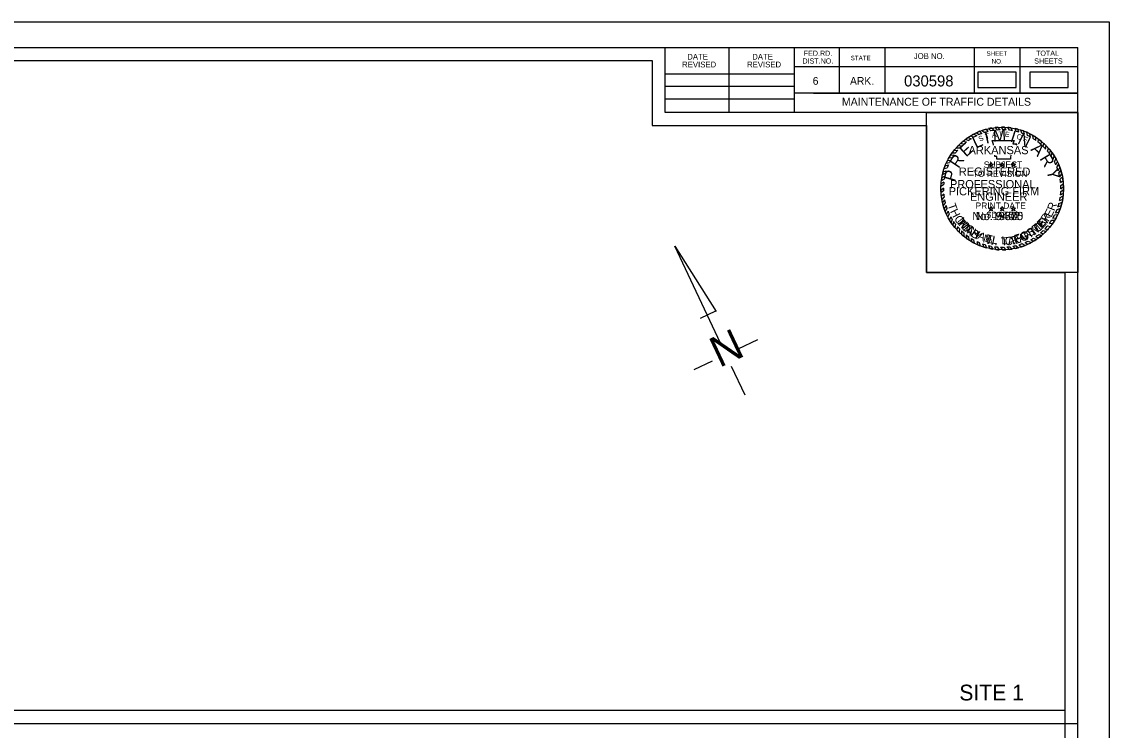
# Model space of a CAD drawing. Extents: x 1368648 to 1927880, y -1037443 to 380209.
# Drawn here: x 1376651 to 1377477, y 379215 to 379753 of the extents above; entities that cross this region are included whole.
import ezdxf

# ---------------------------------------------------------------- set-up
doc = ezdxf.new("R2010")
doc.units = 0
for name, color, linetype in [('Default', 7, 'Continuous'), ('R_Border', 7, 'Continuous'), ('R_Border Notes', 7, 'Continuous'), ('R_Border Title', 7, 'Continuous'), ('R_Draft', 7, 'Continuous'), ('R_No Plot', 7, 'Continuous'), ('STAMP_PE_CRAFTON', 7, 'Continuous'), ('STAMP_PE_FOSTER', 7, 'Continuous'), ('STAMP_PE_SEAL-INFO', 7, 'Continuous'), ('STAMP_PE_TAEGTMEYER', 7, 'Continuous'), ('STAMP_PE_TXT', 7, 'Continuous'), ('STAMP_PRELIMINARY', 7, 'Continuous')]:
    doc.layers.add(name, color=color, linetype=linetype)

msp = doc.modelspace()

# ---------------------------------------------------------------- linework, layer by layer
at = {"layer": 'Default'}
for points in [[(1377377.14, 379702.78), (1377406.31, 379702.78), (1377406.31, 379714.33), (1377377.14, 379714.33)], [(1377416.49, 379702.78), (1377445.66, 379702.78), (1377445.66, 379714.33), (1377416.49, 379714.33)]]:
    msp.add_lwpolyline(points, close=True, dxfattribs=at)
at = {"layer": 'R_Border'}
for p, q in [((1375872.18, 379733.26), (1377453.08, 379733.26)), ((1377139.88, 379683.86), (1377139.88, 379733.26)), ((1377188.28, 379683.86), (1377188.28, 379733.26)), ((1377237.58, 379733.26), (1377237.58, 379683.86)), ((1377271.78, 379733.26), (1377271.78, 379698.56)), ((1377306.48, 379733.26), (1377306.48, 379698.56)), ((1377374.38, 379733.26), (1377374.38, 379698.56)), ((1377409.08, 379733.26), (1377409.08, 379698.56)), ((1377453.08, 378705.96), (1377453.08, 379733.26)), ((1377453.08, 379718.56), (1377237.58, 379718.56)), ((1377453.08, 379718.66), (1377453.08, 379718.66)), ((1377139.88, 379713.16), (1377237.58, 379713.16)), ((1377139.88, 379703.86), (1377237.58, 379703.86)), ((1377453.08, 379698.56), (1377237.58, 379698.56)), ((1377252.38, 379698.56), (1377453.08, 379698.56)), ((1377139.88, 379694.16), (1377237.58, 379694.16)), ((1377453.08, 379683.86), (1377139.88, 379683.86)), ((1377453.08, 379219.61), (1375872.18, 379219.61))]:
    msp.add_line(p, q, dxfattribs=at)
at = {"layer": 'R_Draft'}
for p, q in [((1377147.07, 379582.19), (1377178.49, 379532.68)), ((1377181.8, 379508.63), (1377147.07, 379582.19)), ((1377166.62, 379527.56), (1377178.31, 379533.08)), ((1377195.18, 379504.34), (1377210.08, 379511.38)), ((1377161.7, 379488.53), (1377175.65, 379495.12)), ((1377200.43, 379469.16), (1377190.22, 379490.79))]:
    msp.add_line(p, q, dxfattribs=at)
at = {"layer": 'R_No Plot'}
for points in [[(1375810.14, 379752.73), (1377476.84, 379752.73), (1377476.84, 378686.04), (1375810.14, 378686.04)], [(1377443.08, 379229.61), (1375882.18, 379229.61), (1375882.18, 379723.26), (1377129.88, 379723.26), (1377129.88, 379673.86), (1377217.58, 379673.86), (1377338.08, 379673.86), (1377338.08, 379562.19), (1377443.08, 379562.19)], [(1377443.08, 379229.61), (1375882.18, 379229.61), (1375882.18, 379723.26), (1377129.88, 379723.26), (1377129.88, 379673.86), (1377217.58, 379673.86), (1377338.08, 379673.86), (1377338.08, 379562.19), (1377443.08, 379562.19)], [(1377443.08, 379229.61), (1375882.18, 379229.61), (1375882.18, 379723.26), (1377129.88, 379723.26), (1377129.88, 379673.86), (1377217.58, 379673.86), (1377338.08, 379673.86), (1377338.08, 379562.19), (1377443.08, 379562.19)], [(1377443.08, 379229.61), (1375882.18, 379229.61), (1375882.18, 379723.26), (1377129.88, 379723.26), (1377129.88, 379673.86), (1377217.58, 379673.86), (1377338.08, 379673.86), (1377338.08, 379562.19), (1377443.08, 379562.19)], [(1377443.08, 379229.61), (1375882.18, 379229.61), (1375882.18, 379723.26), (1377129.88, 379723.26), (1377129.88, 379673.86), (1377217.58, 379673.86), (1377338.08, 379673.86), (1377338.08, 379562.19), (1377443.08, 379562.19)], [(1377443.08, 379229.61), (1375882.18, 379229.61), (1375882.18, 379723.26), (1377129.88, 379723.26), (1377129.88, 379673.86), (1377217.58, 379673.86), (1377338.08, 379673.86), (1377338.08, 379562.19), (1377443.08, 379562.19)], [(1377443.08, 379229.61), (1375882.18, 379229.61), (1375882.18, 379723.26), (1377129.88, 379723.26), (1377129.88, 379673.86), (1377217.58, 379673.86), (1377338.08, 379673.86), (1377338.08, 379562.19), (1377443.08, 379562.19)], [(1375882.18, 379723.26), (1377129.88, 379723.26), (1377129.88, 379673.86), (1377217.58, 379673.86), (1377338.08, 379673.86), (1377338.08, 379562.19), (1377443.08, 379562.19), (1377443.08, 378715.96), (1375882.18, 378715.96)], [(1377338.08, 379683.86), (1377453.08, 379683.86), (1377453.08, 379562.19), (1377338.08, 379562.19)]]:
    msp.add_lwpolyline(points, close=True, dxfattribs=at)
at = {"layer": 'STAMP_PE_SEAL-INFO'}
for p, q in [((1377371.7, 379666.1), (1377373.86, 379664.99)), ((1377373.94, 379667.36), (1377376.26, 379666.23)), ((1377376.1, 379668.42), (1377378.04, 379667.04)), ((1377378.64, 379669.49), (1377380.11, 379667.87)), ((1377380.37, 379670.13), (1377382.28, 379668.61)), ((1377383.33, 379671.04), (1377384.77, 379669.31)), ((1377385.27, 379671.53), (1377387.05, 379669.81)), ((1377387.68, 379672.01), (1377389.18, 379670.17)), ((1377390.26, 379672.38), (1377391.66, 379670.46)), ((1377393.94, 379670.61), (1377392.38, 379672.57)), ((1377396.42, 379670.63), (1377395.03, 379672.68)), ((1377398.71, 379670.53), (1377397.42, 379672.65)), ((1377401.24, 379670.27), (1377399.78, 379672.49)), ((1377403.37, 379669.95), (1377402.09, 379672.23)), ((1377406.18, 379669.36), (1377405.31, 379671.65)), ((1377408.19, 379668.81), (1377407.4, 379671.16)), ((1377410.45, 379668.08), (1377409.74, 379670.48)), ((1377412.54, 379667.28), (1377411.82, 379669.76)), ((1377414.85, 379666.25), (1377414.34, 379668.74)), ((1377417.08, 379665.11), (1377416.64, 379667.65)), ((1377419.02, 379663.97), (1377418.82, 379666.48)), ((1377362.39, 379658.8), (1377365.11, 379658.59)), ((1377364.06, 379660.41), (1377366.36, 379659.72)), ((1377365.78, 379661.92), (1377368.43, 379661.41)), ((1377367.67, 379663.55), (1377369.94, 379662.53)), ((1377369.77, 379664.88), (1377371.98, 379663.87)), ((1377387.94, 379662.52), (1377404.66, 379662.52)), ((1377388.55, 379660.99), (1377387.94, 379662.52)), ((1377389.07, 379659.5), (1377388.55, 379660.99)), ((1377389.1, 379658.93), (1377389.07, 379659.5)), ((1377404.66, 379662.52), (1377403.54, 379660.07)), ((1377403.54, 379660.07), (1377406.7, 379660.07)), ((1377406.7, 379660.07), (1377405.98, 379658.93)), ((1377421.19, 379662.54), (1377421.03, 379665.12)), ((1377422.99, 379661.21), (1377423.16, 379663.64)), ((1377425.22, 379659.35), (1377425.32, 379661.96)), ((1377426.79, 379657.88), (1377427.13, 379660.38)), ((1377428.58, 379656.02), (1377428.91, 379658.65)), ((1377355.25, 379649.45), (1377357.7, 379649.55)), ((1377356.48, 379651.45), (1377359.06, 379651.62)), ((1377357.65, 379653.17), (1377360.18, 379653.15)), ((1377359.04, 379655.02), (1377361.79, 379655.13)), ((1377360.77, 379657.08), (1377363.38, 379656.88)), ((1377390.06, 379650.38), (1377389.93, 379651.47)), ((1377391.63, 379650.38), (1377390.06, 379650.38)), ((1377391.63, 379648.23), (1377391.63, 379650.38)), ((1377401.86, 379649.92), (1377401.78, 379648.23)), ((1377402.25, 379651.47), (1377401.86, 379649.92)), ((1377429.95, 379654.44), (1377430.63, 379656.79)), ((1377431.57, 379652.35), (1377432.25, 379654.85)), ((1377432.67, 379650.77), (1377433.56, 379653.09)), ((1377434.21, 379648.29), (1377435.12, 379650.74)), ((1377351.48, 379641.19), (1377353.91, 379641.87)), ((1377352.23, 379643.22), (1377354.76, 379643.95)), ((1377353.15, 379645.38), (1377355.67, 379645.9)), ((1377354.09, 379647.33), (1377356.59, 379647.65)), ((1377401.78, 379648.23), (1377391.63, 379648.23)), ((1377435.21, 379646.45), (1377436.34, 379648.68)), ((1377436.36, 379644.03), (1377437.49, 379646.46)), ((1377437.06, 379642.35), (1377438.38, 379644.52)), ((1377438.04, 379639.6), (1377439.39, 379641.98)), ((1377351.57, 379633.11), (1377349.34, 379632)), ((1377352, 379635.41), (1377349.67, 379634.16)), ((1377350.18, 379636.64), (1377352.53, 379637.6)), ((1377350.7, 379638.68), (1377353.09, 379639.52)), ((1377438.58, 379637.78), (1377440.05, 379640.04)), ((1377439.24, 379634.99), (1377440.84, 379637.22)), ((1377439.59, 379633.09), (1377441.36, 379634.85)), ((1377351.01, 379626.34), (1377348.98, 379624.67)), ((1377351.09, 379628.81), (1377348.99, 379627.53)), ((1377351.28, 379630.94), (1377349.09, 379629.53)), ((1377351.04, 379624.31), (1377349.09, 379622.68)), ((1377439.92, 379630.54), (1377441.78, 379632.22)), ((1377440.08, 379628.45), (1377442.03, 379629.91)), ((1377440.09, 379623.83), (1377442.18, 379625.22)), ((1377440.14, 379625.86), (1377442.17, 379627.47)), ((1377351.21, 379621.83), (1377349.35, 379620.05)), ((1377351.47, 379619.69), (1377349.7, 379617.82)), ((1377351.86, 379617.39), (1377350.16, 379615.55)), ((1377439.18, 379616.86), (1377441.46, 379617.84)), ((1377439.64, 379619.36), (1377441.85, 379620.46)), ((1377439.89, 379621.3), (1377442.06, 379622.59)), ((1377352.33, 379615.3), (1377350.77, 379613.22)), ((1377352.95, 379613.06), (1377351.48, 379610.97)), ((1377353.65, 379610.95), (1377352.25, 379608.89)), ((1377354.48, 379608.81), (1377353.18, 379606.7)), ((1377436.17, 379607.66), (1377438.61, 379608.14)), ((1377437.24, 379610.23), (1377439.65, 379610.89)), ((1377437.91, 379612.13), (1377440.36, 379613.14)), ((1377438.64, 379614.6), (1377441, 379615.61)), ((1377355.34, 379606.9), (1377354.21, 379604.59)), ((1377356.52, 379604.61), (1377355.56, 379602.16)), ((1377357.7, 379602.59), (1377356.78, 379600.23)), ((1377358.71, 379601.03), (1377358.16, 379598.27)), ((1377431.44, 379599.61), (1377433.96, 379599.63)), ((1377433.14, 379602.08), (1377435.53, 379602.05)), ((1377434, 379603.49), (1377436.5, 379603.76)), ((1377435.36, 379605.98), (1377437.8, 379606.32)), ((1377360.11, 379599.08), (1377359.6, 379596.42)), ((1377361.63, 379597.19), (1377361.2, 379594.59)), ((1377363.14, 379595.5), (1377362.84, 379592.89)), ((1377364.76, 379593.87), (1377364.61, 379591.23)), ((1377366.48, 379592.31), (1377366.46, 379589.67)), ((1377423.33, 379591.2), (1377425.67, 379590.47)), ((1377424.68, 379592.32), (1377427.04, 379591.67)), ((1377426.71, 379594.18), (1377428.92, 379593.49)), ((1377427.99, 379595.48), (1377430.37, 379595.05)), ((1377429.9, 379597.64), (1377432.21, 379597.24)), ((1377368.28, 379590.84), (1377368.37, 379588.22)), ((1377369.97, 379589.59), (1377370.15, 379587)), ((1377372.11, 379588.18), (1377372.41, 379585.62)), ((1377373.86, 379587.15), (1377374.31, 379584.59)), ((1377376.26, 379585.9), (1377377.05, 379583.3)), ((1377378.13, 379585.06), (1377378.99, 379582.51)), ((1377380.59, 379584.1), (1377381.63, 379581.59)), ((1377382.64, 379583.42), (1377383.77, 379580.98)), ((1377408.34, 379583.37), (1377410.42, 379581.88)), ((1377410.8, 379584.18), (1377413.02, 379582.84)), ((1377412.9, 379585.01), (1377415.02, 379583.7)), ((1377415.2, 379586.05), (1377417.62, 379584.99)), ((1377417.24, 379587.12), (1377419.32, 379585.95)), ((1377419.31, 379588.34), (1377421.56, 379587.37)), ((1377421.03, 379589.48), (1377423.22, 379588.54)), ((1377385.18, 379582.73), (1377386.24, 379580.4)), ((1377387.16, 379582.3), (1377388.4, 379580.01)), ((1377389.67, 379581.89), (1377390.86, 379579.69)), ((1377391.85, 379581.66), (1377393.22, 379579.51)), ((1377394.27, 379581.52), (1377395.78, 379579.46)), ((1377396.57, 379581.51), (1377398.29, 379579.53)), ((1377399.16, 379581.65), (1377400.79, 379579.75)), ((1377401.35, 379581.88), (1377403.22, 379580.09)), ((1377403.58, 379582.23), (1377405.52, 379580.53)), ((1377406.04, 379582.75), (1377407.93, 379581.12))]:
    msp.add_line(p, q, dxfattribs=at)
for radius, start, end in [(46.61, 117.65441, 120.80988), (44.57, 115.68692, 119.15827), (46.61, 111.31242, 114.70259), (44.57, 110.30864, 113.16588), (46.61, 105.23389, 109.03519), (44.57, 104.03521, 107.36155), (46.61, 99.75254, 102.77648), (44.57, 98.25799, 101.03289), (46.61, 93.93815, 96.55172), (44.57, 92.11016, 95.03666), (46.61, 87.72979, 90.67067), (44.57, 85.96279, 88.9097), (46.61, 81.97315, 84.82355), (44.57, 79.92642, 82.69597), (46.61, 75.31251, 77.94263), (44.57, 73.55748, 76.23144), (46.61, 69.60611, 72.30577), (44.57, 67.62483, 70.50398), (46.61, 63.13288, 66.2704), (44.57, 61.15575, 64.37837), (46.61, 56.90029, 60.09423), (46.61, 135.40208, 138.30314), (44.57, 133.13306, 136.25623), (46.61, 129.73259, 132.53764), (44.57, 127.52969, 130.96829), (46.61, 123.61993, 126.59063), (44.57, 121.97456, 125.11001), (44.57, 54.92383, 58.27016), (44.57, 48.30163, 52.03953), (46.61, 50.3492, 53.71593), (44.57, 42.22116, 45.55119), (46.61, 44.3405, 47.39292), (46.61, 147.00719, 149.89904), (46.61, 141.60556, 144.44865), (44.57, 145.01972, 148.21036), (44.57, 139.30101, 142.58729), (44.57, 36.13503, 39.53106), (46.61, 38.12472, 41.23157), (44.57, 29.90321, 33.66454), (46.61, 31.96138, 35.42937), (46.61, 158.40766, 161.07015), (46.61, 152.86398, 155.51889), (44.57, 156.34018, 159.23194), (44.57, 151.03153, 153.57304), (44.57, 23.77322, 27.22114), (46.61, 25.93909, 29.01247), (44.57, 17.68022, 21.42509), (46.61, 19.95381, 23.31409), (46.61, 170.0003, 172.68778), (46.61, 164.3068, 166.89395), (44.57, 167.90481, 170.90393), (44.57, 162.43309, 165.00133), (44.57, 11.54445, 15.23639), (44.57, 5.7599, 9.06056), (46.61, 13.84205, 17.44468), (46.61, 7.58519, 10.86211), (46.61, 181.72508, 184.16255), (46.61, 175.74093, 178.2066), (44.57, 179.64537, 182.26333), (44.57, 173.73, 176.47337), (44.57, 359.73289, 3.06392), (46.61, 1.72155, 4.72681), (46.61, 355.71562, 358.95694), (46.61, 187.42037, 190.19271), (44.57, 185.45389, 188.23401), (44.57, 191.22736, 193.98583), (44.57, 348.07782, 351.34355), (44.57, 353.86319, 357.12742), (46.61, 349.83047, 353.08845), (46.61, 193.03695, 195.99732), (46.61, 198.89671, 201.62812), (44.57, 196.96751, 199.83526), (44.57, 202.77613, 205.47915), (44.57, 335.6038, 339.18578), (44.57, 341.77699, 345.09248), (46.61, 337.38367, 340.99332), (46.61, 343.89247, 347.03502), (46.61, 204.54793, 207.43282), (46.61, 210.86355, 213.65709), (44.57, 208.78826, 211.79343), (44.57, 214.18375, 217.27474), (44.57, 323.58513, 327.44069), (46.61, 325.44052, 328.98725), (44.57, 329.55488, 333.20757), (46.61, 331.40371, 334.93315), (46.61, 216.61154, 219.49098), (46.61, 222.47995, 225.38008), (44.57, 220.39088, 223.30564), (46.61, 228.36648, 231.34802), (44.57, 226.24938, 229.24068), (44.57, 304.82299, 308.51428), (44.57, 310.77436, 314.31605), (46.61, 312.45177, 315.66328), (44.57, 316.65308, 320.37109), (46.61, 318.28455, 321.80429), (44.57, 232.22904, 234.93361), (46.61, 234.29502, 236.94517), (44.57, 238.22227, 240.83529), (46.61, 240.1977, 242.86128), (44.57, 244.32043, 246.94859), (46.61, 246.57598, 249.15579), (44.57, 250.34912, 253.12157), (44.57, 286.64233, 289.97826), (44.57, 292.87452, 296.11851), (46.61, 294.64808, 298.21662), (44.57, 299.07679, 302.17235), (46.61, 300.62101, 303.87026), (46.61, 306.37206, 310.20799), (46.61, 252.59667, 255.32518), (44.57, 256.50505, 259.11916), (46.61, 258.44328, 261.13983), (44.57, 262.37828, 265.20115), (46.61, 264.19784, 267.10092), (44.57, 268.3215, 271.27698), (46.61, 270.25484, 273.33609), (44.57, 274.61565, 277.44863), (46.61, 276.42389, 279.43574), (44.57, 280.34588, 283.58137), (46.61, 282.31994, 285.37019), (46.61, 288.57086, 291.97334)]:
    msp.add_arc((1377395.58, 379626.07), radius, start, end, dxfattribs=at)
at = {"layer": 'STAMP_PE_TXT'}
for p, q in [((1377386.47, 379643.93), (1377385.48, 379644.65)), ((1377385.48, 379644.65), (1377386.71, 379644.65)), ((1377386.1, 379642.76), (1377386.47, 379643.93)), ((1377387.09, 379643.48), (1377386.1, 379642.76)), ((1377386.71, 379644.65), (1377387.09, 379645.81)), ((1377387.09, 379645.81), (1377387.47, 379644.65)), ((1377388.08, 379642.76), (1377387.09, 379643.48)), ((1377387.47, 379644.65), (1377388.69, 379644.65)), ((1377388.69, 379644.65), (1377387.7, 379643.93)), ((1377387.7, 379643.93), (1377388.08, 379642.76)), ((1377394.96, 379643.93), (1377393.97, 379644.65)), ((1377393.97, 379644.65), (1377395.2, 379644.65)), ((1377394.59, 379642.76), (1377394.96, 379643.93)), ((1377395.58, 379643.48), (1377394.59, 379642.76)), ((1377395.2, 379644.65), (1377395.58, 379645.81)), ((1377395.58, 379645.81), (1377395.96, 379644.65)), ((1377396.57, 379642.76), (1377395.58, 379643.48)), ((1377395.96, 379644.65), (1377397.18, 379644.65)), ((1377397.18, 379644.65), (1377396.19, 379643.93)), ((1377396.19, 379643.93), (1377396.57, 379642.76)), ((1377403.45, 379643.93), (1377402.46, 379644.65)), ((1377402.46, 379644.65), (1377403.69, 379644.65)), ((1377403.07, 379642.76), (1377403.45, 379643.93)), ((1377404.07, 379643.48), (1377403.07, 379642.76)), ((1377403.69, 379644.65), (1377404.07, 379645.81)), ((1377404.07, 379645.81), (1377404.45, 379644.65)), ((1377405.06, 379642.76), (1377404.07, 379643.48)), ((1377404.45, 379644.65), (1377405.67, 379644.65)), ((1377405.67, 379644.65), (1377404.68, 379643.93)), ((1377404.68, 379643.93), (1377405.06, 379642.76)), ((1377386.47, 379610.39), (1377385.48, 379611.11)), ((1377385.48, 379611.11), (1377386.71, 379611.11)), ((1377386.1, 379609.22), (1377386.47, 379610.39)), ((1377387.09, 379609.95), (1377386.1, 379609.22)), ((1377386.71, 379611.11), (1377387.09, 379612.28)), ((1377387.09, 379612.28), (1377387.47, 379611.11)), ((1377388.08, 379609.22), (1377387.09, 379609.95)), ((1377387.47, 379611.11), (1377388.69, 379611.11)), ((1377388.69, 379611.11), (1377387.7, 379610.39)), ((1377387.7, 379610.39), (1377388.08, 379609.22)), ((1377394.96, 379610.39), (1377393.97, 379611.11)), ((1377393.97, 379611.11), (1377395.2, 379611.11)), ((1377394.59, 379609.22), (1377394.96, 379610.39)), ((1377395.58, 379609.95), (1377394.59, 379609.22)), ((1377395.2, 379611.11), (1377395.58, 379612.28)), ((1377395.58, 379612.28), (1377395.96, 379611.11)), ((1377396.57, 379609.22), (1377395.58, 379609.95)), ((1377395.96, 379611.11), (1377397.18, 379611.11)), ((1377397.18, 379611.11), (1377396.19, 379610.39)), ((1377396.19, 379610.39), (1377396.57, 379609.22)), ((1377403.45, 379610.39), (1377402.46, 379611.11)), ((1377402.46, 379611.11), (1377403.69, 379611.11)), ((1377403.07, 379609.22), (1377403.45, 379610.39)), ((1377404.07, 379609.95), (1377403.07, 379609.22)), ((1377403.69, 379611.11), (1377404.07, 379612.28)), ((1377404.07, 379612.28), (1377404.45, 379611.11)), ((1377405.06, 379609.22), (1377404.07, 379609.95)), ((1377404.45, 379611.11), (1377405.67, 379611.11)), ((1377405.67, 379611.11), (1377404.68, 379610.39)), ((1377404.68, 379610.39), (1377405.06, 379609.22))]:
    msp.add_line(p, q, dxfattribs=at)
at = {"layer": 'STAMP_PRELIMINARY'}
msp.add_circle((1377395.58, 379626.07), 46.61, dxfattribs=at)

# ---------------------------------------------------------------- texts
at = {"layer": 'R_Border'}
for s, height, p in [('DATE', 4.396, (1377156.57, 379723.94)), ('DATE', 4.396, (1377205.87, 379723.94)), ('DIST.NO.', 3.91, (1377243.98, 379720.96)), ('FED.RD.', 3.91, (1377244.98, 379726.86)), ('STATE', 3.42, (1377280.58, 379723.46)), ('JOB NO.', 4.396, (1377328.48, 379724.46)), ('SHEET', 3.42, (1377383.68, 379726.86)), ('NO.', 3.42, (1377387.58, 379720.96)), ('SHEETS', 3.91, (1377419.88, 379720.96)), ('TOTAL', 3.91, (1377421.28, 379726.86)), ('REVISED', 4.396, (1377152.67, 379718.04)), ('REVISED', 4.396, (1377201.97, 379718.04)), ('6', 5.86, (1377251.78, 379704.86)), ('ARK.', 5.861, (1377280.08, 379704.86))]:
    msp.add_text(s, height=height, dxfattribs=at).set_placement(p)
at = {"layer": 'R_Border Notes'}
for s, height, p in [('030598', 8.4, (1377321.13, 379703.58)), ('MAINTENANCE OF TRAFFIC DETAILS', 6, (1377273.92, 379688.95))]:
    msp.add_text(s, height=height, dxfattribs=at).set_placement(p)
at = {"layer": 'R_Border Title'}
msp.add_text('SITE 1', height=12, dxfattribs=at).set_placement((1377363.03, 379237.23))
at = {"layer": 'R_Draft'}
msp.add_text('N', height=23.27, rotation=25.27231, dxfattribs=at).set_placement((1377180.97, 379489.71))
at = {"layer": 'STAMP_PE_CRAFTON'}
msp.add_text('No. 12370', height=6.25, dxfattribs=at).set_placement((1377372.89, 379602.05))
for s, rotation, p in [('T', 310.74416, (1377360.41, 379600.56)), ('O', 317.64216, (1377363.74, 379596.5)), ('O', 41.83906, (1377422.75, 379592.27)), ('N', 49.24107, (1377426.99, 379596.18)), ('N', 324.45371, (1377367.97, 379592.58)), ('Y', 331.16864, (1377373.14, 379589)), ('A', 20.51248, (1377408.98, 379584.85)), ('F', 28.78207, (1377413.88, 379586.72)), ('T', 34.11362, (1377418.46, 379589.26)), ('N', 347.47515, (1377383.41, 379584.42)), ('.', 356.89262, (1377389.56, 379583.03)), ('C', 6.01169, (1377397.93, 379582.77)), ('R', 14.81888, (1377403.42, 379583.35))]:
    msp.add_text(s, height=6.25, rotation=rotation, dxfattribs=at).set_placement(p)
at = {"layer": 'STAMP_PE_FOSTER'}
msp.add_text('No. 9402', height=6.25, dxfattribs=at).set_placement((1377375.51, 379602.05))
for s, rotation, p in [('M', 308.33902, (1377361.16, 379601.18)), ('I', 314.18423, (1377365.14, 379596.49)), ('T', 39.41938, (1377421.29, 379592.27)), ('E', 46.96131, (1377425.58, 379596.02)), ('R', 54.5031, (1377429.2, 379600.12)), ('C', 319.87327, (1377366.92, 379594.72)), ('H', 327.72349, (1377371.56, 379591.04)), ('A', 335.72761, (1377376.47, 379588.13)), ('E', 343.5779, (1377382.15, 379585.78)), ('F', 15.86908, (1377405.75, 379584.84)), ('O', 23.71897, (1377410.97, 379586.48)), ('S', 31.72336, (1377416.53, 379589.13)), ('L', 350.81148, (1377387.45, 379584.39)), ('L', 1.26658, (1377395.14, 379583.61)), ('.', 6.80354, (1377400.38, 379583.9))]:
    msp.add_text(s, height=6, rotation=rotation, dxfattribs=at).set_placement(p)
at = {"layer": 'STAMP_PE_TAEGTMEYER'}
for s, rotation, p in [('T', 289.64597, (1377354.05, 379613.62)), ('H', 296.73386, (1377355.85, 379608.7)), ('E', 63.0984, (1377432.81, 379603.73)), ('R', 69.57001, (1377435.3, 379608.64)), ('O', 303.77078, (1377358.81, 379603.16)), ('M', 314.20329, (1377362.09, 379598.4)), ('E', 46.80938, (1377425.77, 379594.95)), ('Y', 53.99864, (1377429.46, 379599.03)), ('A', 321.0594, (1377366.89, 379593.58)), ('S', 327.82385, (1377371.03, 379590.36)), ('E', 17.68363, (1377405.33, 379583.73)), ('G', 23.30524, (1377410.58, 379585.38)), ('T', 31.46601, (1377416.08, 379587.84)), ('M', 39.30005, (1377420.57, 379590.56)), ('N', 344.27273, (1377380.51, 379585.33)), ('.', 350.64643, (1377386.57, 379583.67)), ('T', 3.00609, (1377394.9, 379582.67)), ('A', 8.98261, (1377400.13, 379582.95))]:
    msp.add_text(s, height=6.25, rotation=rotation, dxfattribs=at).set_placement(p)
msp.add_text('No. 19605', height=6.25, dxfattribs=at).set_placement((1377372.89, 379602.05))
at = {"layer": 'STAMP_PE_TXT'}
for s, rotation, p in [('S', 23.5541, (1377378.57, 379661.59)), ('T', 16.311, (1377383.18, 379663.45)), ('A', 9.0679, (1377388, 379664.71)), ('T', 1.82479, (1377392.93, 379665.36)), ('E', 355.20019, (1377397.48, 379665.4)), ('O', 342.25065, (1377406.11, 379664.02)), ('F', 335.00755, (1377410.94, 379662.33))]:
    msp.add_text(s, height=3.91, rotation=rotation, dxfattribs=at).set_placement(p)
for s, p in [('ARKANSAS', (1377370.04, 379652.12)), ('REGISTERED', (1377362.66, 379635.77)), ('PROFESSIONAL', (1377355.92, 379626.27)), ('ENGINEER', (1377371.12, 379616.76))]:
    msp.add_text(s, height=6.25, dxfattribs=at).set_placement(p)
at = {"layer": 'STAMP_PRELIMINARY'}
for s, rotation, p in [('I', 12.52485, (1377383.26, 379660)), ('M', 3.10738, (1377388.76, 379661.55)), ('I', 342.31637, (1377401.09, 379661.88)), ('N', 333.9382, (1377406.63, 379660.51)), ('E', 42.35784, (1377368.21, 379649.55)), ('L', 25.51305, (1377375.62, 379656.21)), ('A', 315.65789, (1377416.8, 379655.39)), ('R', 56.22922, (1377362.43, 379640.89)), ('R', 301.38306, (1377423.64, 379648.82)), ('Y', 283.25926, (1377429.09, 379639.88)), ('P', 73.91301, (1377359.68, 379630.77))]:
    msp.add_text(s, height=9, rotation=rotation, dxfattribs=at).set_placement(p)
for s, height, p in [('SUBJECT', 4.8, (1377381.58, 379641.81)), ('TO REVISION', 4.8, (1377373.25, 379634.89)), ('PICKERING FIRM', 6.25, (1377354.94, 379620.88)), ('PRINT DATE', 4.8, (1377375.36, 379610.65)), ('$DATE$', 4.8, (1377383.75, 379603.72))]:
    msp.add_text(s, height=height, dxfattribs=at).set_placement(p)

doc.saveas('drawing.dxf')
